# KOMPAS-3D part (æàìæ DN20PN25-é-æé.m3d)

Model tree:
1. Объединить компоненты:1  (labels: СЕНС DN20PN25-В)
2. Эскиз:1
3. Операция выдавливания:1
     Расстояние 1 = 14
4. Фаска:1
     Угол = 45; Длина 1 = 2; Длина 2 = 2

Referenced files in D:\Савин\!СЕНСОР\3D для заказчика\!Новый перечень\СЕНС\3. СЕНС-В\DN20\: СЕНС DN20PN25-В.a3d
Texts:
  СЕНС DN20PN25-В-СВ
  ООО НПП Сенсор
  СЕНС DN20PN25-В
